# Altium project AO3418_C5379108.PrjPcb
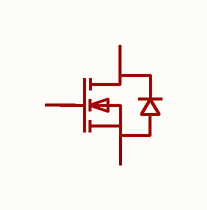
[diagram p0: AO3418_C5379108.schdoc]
1 sheet, 1 parts. Net scope: global (net labels, ports and power ports of the same name join across sheets).

## Sheet AO3418_C5379108.schdoc
size 127 x 101 mm

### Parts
Q?  ao3418_c5379108  [SOT-23-3_L2.9-W1.6-P1.90-LS2.8-BR]  (value not drawn)

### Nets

Not connected (* = marked no-connect by the designer): Q? 1(G) 2(S) 3(D)

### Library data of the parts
Q? = ao3418_c5379108: 数量:1个N沟道;漏源电压(Vdss):30V;连续漏极电流(Id):3.8A;导通电阻(RDS(on)):45mΩ@10V;耗散功率(Pd):278mW;阈值电压(Vgs(th)):1V;; Manufacturer: MSKSEMI(美森科); ManufacturerPart: AO3418; AddInBom: yes; ModelId: 89cb27a44ab2466697082bb9fd73a7d0; ModelName: SOT-23-3L_L2.9-W1.6-H1.1-LS2.8-P0.95; ModelTransform: 114.173,110.236,0,90,0,0,0,0,0; Number: 1个N沟道; Drain to Source Voltage: 30V; Current - Continuous Drain(Id): 3.8A; Pd - Power Dissipation: 278mW; Gate Threshold Voltage (Vgs(th)): 1V; Gate Charge(Qg): 3.1nC@10V; Input Capacitance(Ciss): 245pF; Reverse Transfer Capacitance (Crss@Vds): 78pF; Output Capacitance(Coss): 40pF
